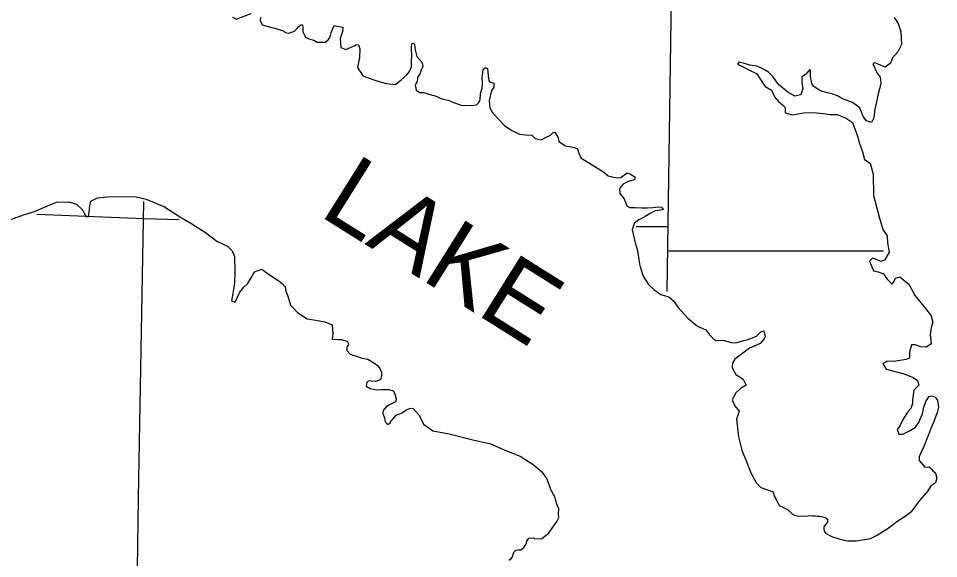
# Model space of a CAD drawing. Extents: x -492261 to -432772, y 1441225 to 1452922.
# Drawn here: x -463526 to -463261.3, y 1451090.8 to 1451246.2 of the extents above; entities that cross this region are included whole.
import ezdxf

# ---------------------------------------------------------------- set-up
doc = ezdxf.new("R2010")
doc.units = 0
doc.layers.add('Default', color=7, linetype='Continuous')

msp = doc.modelspace()

# ---------------------------------------------------------------- linework, layer by layer
at = {"layer": 'Default'}
for points in [[(-463339.09, 1451740.72), (-463337.5, 1451641.25), (-463337.22, 1451633.29), (-463336.18, 1451489.83), (-463336.25, 1451481.82), (-463337.26, 1451337.74), (-463337.04, 1451330.58), (-463339.5, 1451167.68)], [(-463464.43, 1451246.53), (-463463.35, 1451245.96), (-463459.07, 1451247.62)], [(-463456.39, 1451246.53), (-463456.5, 1451245.62), (-463455.87, 1451244.36), (-463453.08, 1451243.56), (-463451.71, 1451243.15), (-463449.77, 1451242.58), (-463449.26, 1451242.12), (-463448.17, 1451241.9), (-463446.57, 1451242.52), (-463446, 1451243.1), (-463445.37, 1451243.84), (-463444.8, 1451244.35), (-463444.29, 1451244.3), (-463444.23, 1451243.55), (-463444.18, 1451242.35), (-463443.44, 1451240.81), (-463442.47, 1451240.29), (-463441.04, 1451239.95), (-463440.07, 1451239.38), (-463437.79, 1451239.38), (-463436.93, 1451240.06), (-463436.53, 1451240.52), (-463436.36, 1451240.92), (-463436.07, 1451242.12), (-463435.16, 1451244.18), (-463433.73, 1451243.89), (-463432.65, 1451243.66), (-463432.82, 1451242.46), (-463433.45, 1451240.4), (-463433.28, 1451237.83), (-463431.79, 1451237.26), (-463429.4, 1451238.34), (-463428.83, 1451238.63), (-463428.14, 1451238.57), (-463427.8, 1451237.43), (-463427.91, 1451234.97), (-463428.43, 1451232.05), (-463426.95, 1451229.65), (-463423.52, 1451228.45), (-463421.58, 1451227.82), (-463420.1, 1451227.42), (-463417.53, 1451227.19), (-463415.88, 1451228.5), (-463414.28, 1451229.99), (-463413.54, 1451230.9), (-463412.96, 1451232.22), (-463412.91, 1451233.76), (-463412.79, 1451235.42), (-463412.96, 1451237.48), (-463412.9, 1451238.34), (-463412.79, 1451238.85), (-463412.44, 1451239.03), (-463412.05, 1451238.63), (-463411.88, 1451237.14), (-463411.42, 1451235.25), (-463409.99, 1451233.59), (-463409.65, 1451232.33), (-463410.17, 1451231.3), (-463410.51, 1451230.1), (-463411.2, 1451229.24), (-463411.25, 1451227.87), (-463411.37, 1451227.87), (-463411.88, 1451226.96), (-463411.71, 1451226.1), (-463411.6, 1451225.58), (-463410.63, 1451224.9), (-463409.37, 1451224.84), (-463407.89, 1451224.38), (-463406.12, 1451223.87), (-463404.24, 1451223.01), (-463402.41, 1451222.66), (-463400.53, 1451221.92), (-463398.59, 1451221.23), (-463395.79, 1451221.17), (-463394.25, 1451221.35)], [(-463274.03, 1451246.42), (-463272.89, 1451244.71), (-463272.1, 1451242.42), (-463271.98, 1451238.64), (-463273.01, 1451236.59), (-463274.56, 1451234.81), (-463275.13, 1451233.27), (-463276.67, 1451232.18), (-463278.67, 1451232.98), (-463279.58, 1451233.44), (-463280.15, 1451233.1), (-463278.95, 1451230.47), (-463278.04, 1451229.27), (-463277.87, 1451227.38), (-463278.79, 1451224.06), (-463279.13, 1451222.23), (-463279.65, 1451220.11), (-463279.93, 1451217.6), (-463280.56, 1451216.28), (-463282.05, 1451216.74), (-463282.96, 1451218), (-463283.93, 1451220.46), (-463286.09, 1451221.95), (-463288.89, 1451223.03), (-463290.37, 1451223.89), (-463291.97, 1451224.52), (-463293.23, 1451224.75), (-463295.05, 1451225.21), (-463296.82, 1451226.3), (-463297.16, 1451226.58), (-463297.79, 1451227.38), (-463297.9, 1451228.47), (-463298.02, 1451228.87), (-463298.13, 1451229.39), (-463298.13, 1451230.59), (-463298.13, 1451231.16), (-463298.42, 1451231.39), (-463298.87, 1451230.82), (-463299.56, 1451230.07), (-463300.64, 1451229.39), (-463300.64, 1451227.67), (-463300.36, 1451226.07), (-463300.93, 1451224.24), (-463302.64, 1451223.78), (-463304.58, 1451224.87), (-463306.3, 1451226.3), (-463307.38, 1451227.21), (-463308.86, 1451229.39), (-463310.23, 1451230.7), (-463311.37, 1451231.39)], [(-463311.37, 1451231.39), (-463312.23, 1451231.85), (-463313.6, 1451232.42), (-463315.54, 1451232.76), (-463317.08, 1451233.22), (-463318.73, 1451233.62), (-463319.13, 1451232.99), (-463317.53, 1451232.25), (-463315.71, 1451231.33), (-463313.65, 1451230.3), (-463312.12, 1451228.07), (-463311.15, 1451226.59), (-463309.38, 1451225.5), (-463308.52, 1451223.67), (-463307.38, 1451222.24), (-463306.18, 1451221.32), (-463305.39, 1451220.58), (-463305.44, 1451219.03), (-463303.33, 1451218.46), (-463300.14, 1451218.98), (-463297.34, 1451219.09), (-463294.49, 1451218.86), (-463292.49, 1451218.52), (-463290.43, 1451218.52), (-463288.04, 1451217.54), (-463286.04, 1451216.28), (-463284.62, 1451212.28), (-463284.1, 1451210.51), (-463283.19, 1451207.76), (-463282.57, 1451205.64), (-463280.97, 1451204.56), (-463280.12, 1451201.41), (-463280.01, 1451195.29), (-463278.3, 1451188.77), (-463277.27, 1451185.51), (-463276.08, 1451183.68), (-463276.02, 1451181.67), (-463275.45, 1451178.93), (-463276.88, 1451176.64), (-463277.91, 1451176.3), (-463279.11, 1451176.81), (-463280.25, 1451177.21), (-463281.16, 1451176.41), (-463280.02, 1451173.55), (-463278.65, 1451173.32), (-463277.17, 1451172.75), (-463276.03, 1451171.21), (-463274.6, 1451169.78), (-463274.03, 1451170.63), (-463273.63, 1451171.43), (-463272.43, 1451171.89), (-463269.86, 1451169.72), (-463267.98, 1451166.4), (-463265.08, 1451162.74), (-463263.42, 1451160.68), (-463262.91, 1451158.79), (-463263.37, 1451157.25), (-463263.65, 1451155.13), (-463263.43, 1451152.55), (-463264.74, 1451151.64), (-463266.4, 1451151.75), (-463268.05, 1451152.33), (-463269.08, 1451152.33), (-463269.65, 1451150.21), (-463269.65, 1451148.5), (-463270.62, 1451148.04), (-463273.53, 1451147.64), (-463276.16, 1451147.47), (-463277.3, 1451146.84), (-463276.33, 1451145.35), (-463271.2, 1451143.98), (-463268.63, 1451142.89), (-463267.37, 1451142.09), (-463266.97, 1451140.71), (-463268.35, 1451139.29), (-463268.8, 1451136.48), (-463268.81, 1451135.45), (-463269.26, 1451134.02), (-463270.23, 1451132.94), (-463271.61, 1451130.59), (-463272.46, 1451128.99), (-463273.15, 1451127.96), (-463272.75, 1451126.59), (-463271.55, 1451126.59), (-463269.44, 1451127.62), (-463268.01, 1451128.53), (-463267.55, 1451129.16), (-463266.98, 1451129.96), (-463266.64, 1451130.7), (-463265.95, 1451132.48), (-463265.5, 1451134.42), (-463264.75, 1451136.48), (-463264.52, 1451136.6), (-463264.24, 1451137.05), (-463263.95, 1451137.45), (-463263.27, 1451137.68), (-463262.24, 1451137.22), (-463261.61, 1451136.25), (-463261.27, 1451134.36), (-463261.67, 1451132.88), (-463262.64, 1451130.25)], [(-463394.25, 1451221.35), (-463393.62, 1451221.92), (-463393.17, 1451222.72), (-463393.05, 1451224.61), (-463392.59, 1451226.15), (-463392.53, 1451227.52), (-463392.59, 1451229.35), (-463392.36, 1451230.5), (-463392.3, 1451231.47), (-463391.67, 1451232.04), (-463391.05, 1451231.81), (-463390.88, 1451229.64), (-463390.71, 1451228.44), (-463390.48, 1451227.98), (-463389.22, 1451227.52), (-463389.28, 1451226.44), (-463389.91, 1451225.46), (-463390.54, 1451222.55), (-463390.37, 1451220.6), (-463389.8, 1451219.34), (-463388.15, 1451217.51), (-463386.15, 1451215.39), (-463384.1, 1451213.96), (-463381.81, 1451212.88), (-463380.1, 1451212.7), (-463378.28, 1451212.59), (-463377.36, 1451211.67), (-463375.59, 1451211.27), (-463374.4, 1451211.96), (-463372.97, 1451212.59), (-463372.17, 1451213.33), (-463371.65, 1451213.5), (-463370.86, 1451212.07), (-463370.57, 1451210.76), (-463368.58, 1451209.56), (-463367.49, 1451209.33), (-463366.06, 1451209.1), (-463365.21, 1451208.7), (-463364.75, 1451207.38), (-463364.07, 1451206.01), (-463360.42, 1451203.78), (-463357.62, 1451201.94), (-463356.37, 1451200.86), (-463353.86, 1451200.34), (-463352.72, 1451200.4), (-463350.89, 1451201.77), (-463349.92, 1451201.37), (-463348.66, 1451200.57), (-463348.72, 1451199.77), (-463350.55, 1451199.31), (-463352.03, 1451198.51), (-463353.06, 1451197.25), (-463352.95, 1451195.82), (-463351.69, 1451194.28), (-463351.01, 1451192.28), (-463350.1, 1451191.76), (-463348.56, 1451191.76), (-463346.73, 1451191.7), (-463345.02, 1451191.7), (-463343.48, 1451191.82), (-463341.93, 1451191.99), (-463341.02, 1451191.93), (-463340.45, 1451191.3), (-463341.31, 1451191.07), (-463342.79, 1451190.84), (-463344.28, 1451190.04), (-463345.65, 1451189.24), (-463346.73, 1451188.67), (-463347.47, 1451188.27), (-463348.9, 1451187.24), (-463349.47, 1451185.41), (-463348.62, 1451181.64), (-463347.94, 1451179.4), (-463347.31, 1451175.46), (-463347.14, 1451174.77), (-463346.29, 1451172.08), (-463344.69, 1451169.62), (-463343.21, 1451168.19), (-463341.21, 1451166.82), (-463338.93, 1451166.07), (-463337.56, 1451164.93), (-463336.3, 1451163.16), (-463334.25, 1451160.92), (-463333.45, 1451160.01), (-463330.6, 1451157.66), (-463328.2, 1451156.63), (-463327.06, 1451155.09), (-463325.52, 1451153.54), (-463323.13, 1451153.6), (-463321.07, 1451152.97), (-463319.59, 1451152.91), (-463317.65, 1451153.43), (-463316.05, 1451153.88), (-463313.71, 1451154.8), (-463312.45, 1451156), (-463311.6, 1451156.29), (-463311.2, 1451154.57), (-463311.48, 1451154.05), (-463312.63, 1451152.68), (-463313.65, 1451152.17), (-463315.65, 1451151.31)], [(-463528.74, 1451188.15), (-463524.23, 1451189.8), (-463521.43, 1451190.61), (-463518.52, 1451191.86), (-463515.1, 1451193.29), (-463511.56, 1451193.41), (-463509.28, 1451192.72), (-463507.45, 1451191.06), (-463506.65, 1451189.17), (-463505.85, 1451189.17), (-463505.63, 1451190.43), (-463505.45, 1451192.32), (-463505.22, 1451193.58), (-463503.28, 1451194.55), (-463499.4, 1451194.95), (-463492.1, 1451194.83), (-463489.24, 1451194.2), (-463483.99, 1451192.03), (-463479.43, 1451189.05), (-463476.12, 1451187.1), (-463472.18, 1451184.64), (-463468.93, 1451182.07), (-463465.91, 1451180.64), (-463464.48, 1451179.32), (-463463.86, 1451177.66), (-463463.8, 1451173.49), (-463463.86, 1451170), (-463464.26, 1451167.65), (-463464.72, 1451164.96), (-463463.69, 1451164.62), (-463462.27, 1451167.42), (-463461.12, 1451168.91), (-463460.15, 1451169.82)], [(-463490.04, 1451193.51), (-463491.53, 1451108.34)], [(-463479.77, 1451188.25), (-463489.82, 1451188.54), (-463520.75, 1451189.8)], [(-463339.2, 1451186.27), (-463348.27, 1451186.21)], [(-463277.11, 1451179.27), (-463338.92, 1451179.23)], [(-463460.15, 1451169.82), (-463459.07, 1451171.6), (-463458.09, 1451173.26), (-463455.98, 1451174.06), (-463453.76, 1451172.45), (-463451.42, 1451170.91), (-463450.11, 1451169.94), (-463449.25, 1451168.96), (-463449.08, 1451167.76), (-463448.51, 1451166.28), (-463447.77, 1451163.7), (-463445.66, 1451161.53), (-463442.92, 1451159.75), (-463440.41, 1451159.41), (-463437.9, 1451158.95), (-463435.79, 1451158.03), (-463435.51, 1451155.57), (-463435.79, 1451153.97), (-463433.97, 1451153.8), (-463433.05, 1451153.8), (-463431.57, 1451153.34), (-463431.28, 1451153.11), (-463431.06, 1451152.26), (-463431.51, 1451151.68), (-463431.51, 1451150.71), (-463430.54, 1451149.62), (-463427.12, 1451148.42), (-463425.52, 1451148.14), (-463423.75, 1451147.16), (-463422.73, 1451146.36), (-463422.1, 1451145.68), (-463421.59, 1451144.47), (-463421.53, 1451143.33), (-463421.87, 1451142.36), (-463422.16, 1451142.13), (-463423.24, 1451141.79), (-463424.39, 1451141.9), (-463425.13, 1451141.96), (-463425.76, 1451141.56), (-463425.93, 1451140.41), (-463424.79, 1451139.73), (-463423.07, 1451139.38), (-463421.59, 1451139.44), (-463419.94, 1451139.44), (-463419.48, 1451139.5), (-463418.17, 1451139.04), (-463417.71, 1451138.24), (-463417.31, 1451136.75), (-463417.54, 1451135.89), (-463419.25, 1451135.04), (-463420.34, 1451134.41), (-463421.08, 1451133.38), (-463421.14, 1451132.46), (-463420.74, 1451131.26), (-463420.51, 1451130.17), (-463419.77, 1451129.43), (-463418.97, 1451130), (-463418.74, 1451130.57), (-463418.34, 1451130.92), (-463417.26, 1451132.17), (-463415.83, 1451132.69), (-463414.29, 1451133.66), (-463413.38, 1451134), (-463412.58, 1451134.06), (-463411.78, 1451133.26), (-463410.69, 1451132.12), (-463409.5, 1451129.48), (-463406.82, 1451127.6), (-463402.08, 1451126.74), (-463395.23, 1451125.02), (-463390.21, 1451123.87), (-463385.59, 1451121.81), (-463381.65, 1451120.27), (-463377.89, 1451117.92), (-463375.55, 1451115.92), (-463373.95, 1451113.74), (-463372.93, 1451110.83)], [(-463315.65, 1451151.31), (-463317.25, 1451150.17), (-463319.88, 1451148.17), (-463320.56, 1451147.02), (-463320.62, 1451145.71), (-463319.65, 1451143.76), (-463317.48, 1451142.44), (-463316.63, 1451140.67), (-463318.23, 1451139.7), (-463319.6, 1451138.5), (-463320.69, 1451136.44), (-463319.94, 1451134.72), (-463318.69, 1451133.24), (-463319.38, 1451130.89), (-463319.26, 1451129.17), (-463318.81, 1451125.86), (-463317.84, 1451121.97), (-463316.42, 1451118.48), (-463315.22, 1451115.33), (-463313.63, 1451112.47)], [(-463262.64, 1451130.25), (-463263.39, 1451128.47), (-463264.25, 1451126.24), (-463264.87, 1451124.81), (-463265.45, 1451123.27), (-463266.42, 1451121.27), (-463266.82, 1451120.07), (-463266.88, 1451119.04), (-463265.22, 1451117.15), (-463264.02, 1451117.2), (-463263.28, 1451116.63), (-463263.17, 1451116.46), (-463262.94, 1451116.06), (-463262.48, 1451115.72), (-463262.2, 1451115.26), (-463262.03, 1451115.03), (-463261.74, 1451114), (-463261.91, 1451113.71), (-463262.2, 1451112.63), (-463263.34, 1451111.88)], [(-463379.18, 1451096.69), (-463377.87, 1451096.76), (-463377.58, 1451096.48), (-463375.47, 1451096.57), (-463374.9, 1451097.03), (-463374.05, 1451097.67), (-463373.54, 1451098.02), (-463373.09, 1451098.65), (-463372.42, 1451099.58), (-463371.8, 1451100.5), (-463371.13, 1451101.48), (-463370.57, 1451102.63), (-463370.59, 1451103.66), (-463370.55, 1451105.09), (-463371.08, 1451106.51), (-463371.38, 1451107.54), (-463371.62, 1451108.17), (-463371.73, 1451108.56), (-463372.93, 1451110.83)], [(-463313.63, 1451112.47), (-463312.4, 1451111.27), (-463311.03, 1451110.83), (-463308.9, 1451110), (-463308.54, 1451108.8), (-463307.96, 1451107.78), (-463307.14, 1451106.13), (-463305.93, 1451105.52), (-463304.78, 1451104.9), (-463303.22, 1451103.49), (-463301.67, 1451103.06), (-463298.81, 1451103.15), (-463298.19, 1451103.22), (-463297.5, 1451103.17), (-463296.81, 1451103.12), (-463296.24, 1451103.07), (-463295.56, 1451103.02), (-463294.93, 1451102.91), (-463294.3, 1451102.75), (-463293.95, 1451102.64), (-463293.66, 1451102.47), (-463293.26, 1451102.14), (-463293.2, 1451101.74), (-463293.19, 1451101.28), (-463293.47, 1451101.1), (-463294.15, 1451100.07), (-463294.26, 1451099.95), (-463294.31, 1451099.15), (-463294.07, 1451098.58), (-463293.72, 1451098.01), (-463291.59, 1451096.95), (-463290.56, 1451096.68), (-463288.55, 1451096.08), (-463287.35, 1451095.98), (-463284.95, 1451095.95), (-463280.9, 1451096.63), (-463279.09, 1451097.51), (-463276.08, 1451099.38), (-463274.72, 1451100.31), (-463273.25, 1451101.48), (-463271.21, 1451102.87), (-463268.95, 1451104.45), (-463268.27, 1451105.31), (-463267.54, 1451106.35), (-463266.7, 1451107.56), (-463266.03, 1451108.32), (-463265.35, 1451109.07), (-463264.73, 1451109.71), (-463264.51, 1451109.99), (-463263.34, 1451111.88)], [(-463491.53, 1451108.34), (-463492.51, 1451040.46), (-463490.8, 1450888.59)], [(-463384.93, 1451090.38), (-463384.25, 1451090.85), (-463383.91, 1451091.37), (-463383.69, 1451092.06), (-463383.36, 1451092.8), (-463382.91, 1451093.21), (-463382.17, 1451093.39), (-463381.43, 1451093.34), (-463380.58, 1451093.98), (-463380.18, 1451094.62), (-463379.85, 1451095.25), (-463379.74, 1451095.82), (-463379.18, 1451096.69)]]:
    msp.add_lwpolyline(points, dxfattribs=at)

# ---------------------------------------------------------------- texts
msp.add_text('LAKE', height=21.12, rotation=327.8937, dxfattribs=at).set_placement((-463439.84, 1451189.7))

doc.saveas('drawing.dxf')
